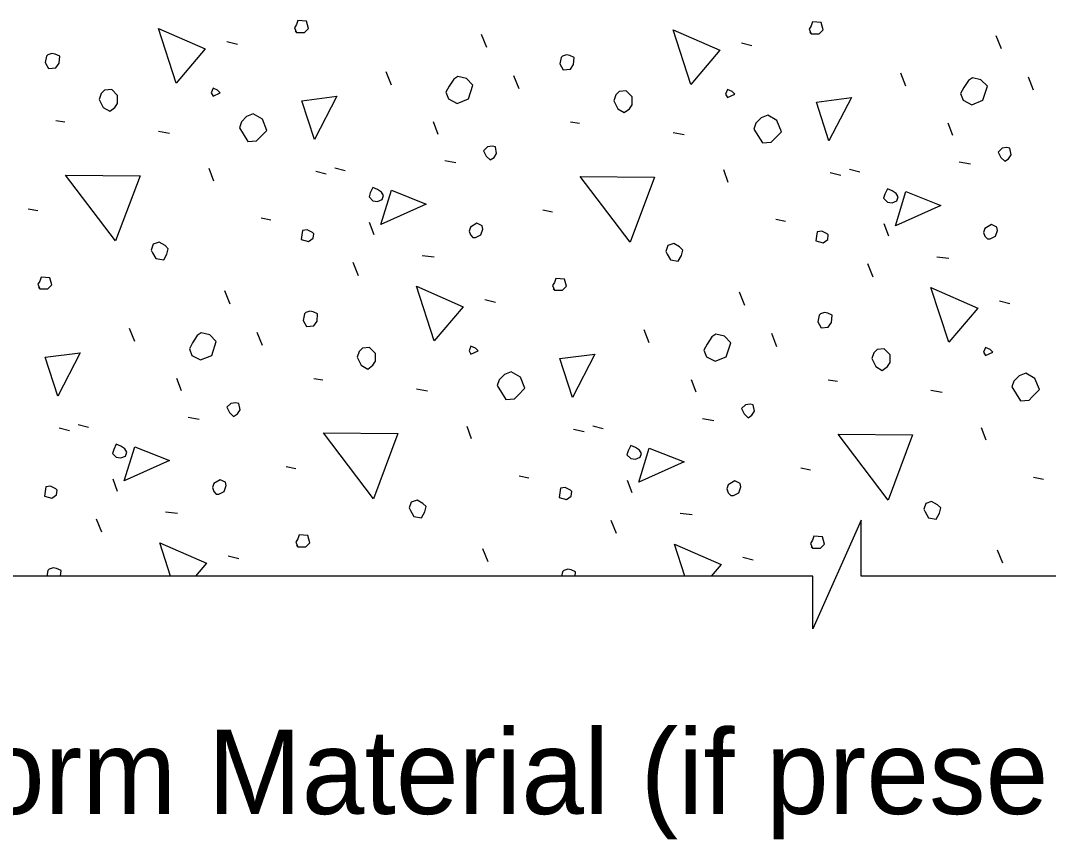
# Model space of a CAD drawing. Extents: x 0 to 15.4, y 0 to 9.7.
# Drawn here: x 4.079 to 5, y 1.736 to 2.469 of the extents above; entities that cross this region are included whole.
import ezdxf

# ---------------------------------------------------------------- set-up
doc = ezdxf.new("R2010")
doc.units = 0
doc.layers.add('Dimension', color=7, linetype='Continuous')
doc.layers.add('Miscellaneous', color=7, linetype='Continuous')

msp = doc.modelspace()

# ---------------------------------------------------------------- linework, layer by layer
at = {"layer": 'Dimension'}
for points in [[(4.21342, 1.97126), (3.76363, 1.97126), (3.76363, 2.02147), (3.7205, 1.92417), (3.7205, 1.97126), (3.21967, 1.97126)], [(5.47696, 1.97126), (4.8318, 1.97126), (4.8318, 2.02147), (4.78868, 1.92417), (4.78868, 1.97126), (4.21342, 1.97126)]]:
    msp.add_lwpolyline(points, dxfattribs=at)
at = {"layer": 'Miscellaneous'}
for p, q in [((4.26383, 2.45024), (4.27325, 2.44788)), ((4.49658, 2.44494), (4.49187, 2.45672)), ((4.72462, 2.44906), (4.73405, 2.44671)), ((4.95738, 2.44376), (4.95267, 2.45554)), ((4.41114, 2.41135), (4.40643, 2.42314)), ((4.87194, 2.41017), (4.86722, 2.42196)), ((4.52546, 2.40781), (4.52074, 2.4196)), ((4.98625, 2.40664), (4.98154, 2.41842)), ((4.11062, 2.37953), (4.11887, 2.37835)), ((4.45298, 2.36716), (4.44885, 2.37835)), ((4.57142, 2.37835), (4.57967, 2.37717)), ((4.91378, 2.36598), (4.90965, 2.37717)), ((4.20254, 2.3701), (4.21256, 2.36833)), ((4.66334, 2.36892), (4.67336, 2.36716)), ((4.45887, 2.34359), (4.46889, 2.34182)), ((4.91967, 2.34241), (4.92969, 2.34064)), ((4.25204, 2.32532), (4.24792, 2.33651)), ((4.34338, 2.33416), (4.3528, 2.3318)), ((4.36046, 2.3371), (4.36989, 2.33475)), ((4.71284, 2.32414), (4.70871, 2.33534)), ((4.80417, 2.33298), (4.8136, 2.33062)), ((4.82126, 2.33593), (4.83069, 2.33357)), ((4.08587, 2.30057), (4.09471, 2.2988)), ((4.29447, 2.29232), (4.30331, 2.29055)), ((4.54667, 2.29939), (4.55551, 2.29762)), ((4.39582, 2.277), (4.3917, 2.2882)), ((4.75527, 2.29114), (4.7641, 2.28937)), ((4.85662, 2.27582), (4.85249, 2.28702)), ((4.43884, 2.25873), (4.44944, 2.25755)), ((4.89963, 2.25755), (4.91024, 2.25638)), ((4.38168, 2.24047), (4.37696, 2.25225)), ((4.84248, 2.23929), (4.83776, 2.25107)), ((4.26677, 2.21513), (4.26206, 2.22691)), ((4.49482, 2.21925), (4.50424, 2.2169)), ((4.72757, 2.21395), (4.72286, 2.22573)), ((4.95561, 2.21807), (4.96504, 2.21572)), ((4.18133, 2.18154), (4.17662, 2.19333)), ((4.64213, 2.18036), (4.63741, 2.19215)), ((4.29565, 2.178), (4.29093, 2.18979)), ((4.75644, 2.17683), (4.75173, 2.18861)), ((4.22317, 2.13735), (4.21904, 2.14854)), ((4.34161, 2.14854), (4.34986, 2.14736)), ((4.68397, 2.13617), (4.67984, 2.14736)), ((4.80241, 2.14736), (4.81066, 2.14619)), ((4.43353, 2.13911), (4.44355, 2.13735)), ((4.89433, 2.13794), (4.90435, 2.13617)), ((4.22906, 2.11378), (4.23908, 2.11201)), ((4.68986, 2.1126), (4.69988, 2.11083)), ((4.11357, 2.10435), (4.12299, 2.10199)), ((4.13066, 2.10729), (4.14008, 2.10494)), ((4.48303, 2.09433), (4.47891, 2.10553)), ((4.57436, 2.10317), (4.58379, 2.10081)), ((4.59145, 2.10612), (4.60088, 2.10376)), ((4.94383, 2.09315), (4.9397, 2.10435)), ((4.31686, 2.06958), (4.3257, 2.06781)), ((4.77766, 2.0684), (4.7865, 2.06664)), ((4.16601, 2.04719), (4.16189, 2.05839)), ((4.52546, 2.06133), (4.5343, 2.05956)), ((4.62681, 2.04601), (4.62268, 2.05721)), ((4.98625, 2.06015), (4.99509, 2.05839)), ((4.20903, 2.02892), (4.21963, 2.02774)), ((4.66982, 2.02774), (4.68043, 2.02657)), ((4.15187, 2.01066), (4.14715, 2.02244)), ((4.61267, 2.00948), (4.60795, 2.02126)), ((4.26501, 1.98944), (4.27443, 1.98709)), ((4.49776, 1.98414), (4.49305, 1.99592)), ((4.7258, 1.98826), (4.73523, 1.98591)), ((4.95856, 1.98296), (4.95385, 1.99475))]:
    msp.add_line(p, q, dxfattribs=at)
for points in [[(4.32629, 2.45849), (4.33336, 2.45849), (4.33689, 2.46203), (4.33513, 2.46851), (4.32747, 2.4691), (4.32629, 2.46556), (4.32452, 2.46262), (4.32629, 2.45849), (4.32511, 2.45967)], [(4.78709, 2.45731), (4.79416, 2.45731), (4.79769, 2.46085), (4.79592, 2.46733), (4.78826, 2.46792), (4.78709, 2.46438), (4.78532, 2.46144), (4.78709, 2.45731), (4.78591, 2.45849)], [(4.21845, 2.41312), (4.20254, 2.46203), (4.24438, 2.44376), (4.21845, 2.41312)], [(4.67925, 2.41194), (4.66334, 2.46085), (4.70518, 2.44258), (4.67925, 2.41194)], [(4.10119, 2.43138), (4.10414, 2.42608), (4.11062, 2.42667), (4.11357, 2.4308), (4.11416, 2.43728), (4.11003, 2.43905), (4.10708, 2.43963), (4.10355, 2.43846), (4.10237, 2.43728), (4.10119, 2.43138)], [(4.56199, 2.43021), (4.56494, 2.4249), (4.57142, 2.42549), (4.57436, 2.42962), (4.57495, 2.4361), (4.57083, 2.43787), (4.56788, 2.43846), (4.56435, 2.43728), (4.56317, 2.4361), (4.56199, 2.43021)], [(4.46241, 2.39898), (4.47007, 2.39485), (4.48008, 2.39898), (4.48421, 2.41135), (4.47832, 2.41724), (4.47066, 2.41901), (4.46712, 2.41665), (4.463, 2.41017), (4.46005, 2.40487), (4.46241, 2.39898)], [(4.9232, 2.3978), (4.93086, 2.39367), (4.94088, 2.3978), (4.94501, 2.41017), (4.93911, 2.41606), (4.93145, 2.41783), (4.92792, 2.41547), (4.92379, 2.40899), (4.92085, 2.40369), (4.9232, 2.3978)], [(4.14951, 2.39839), (4.15305, 2.39132), (4.15894, 2.38778), (4.16365, 2.39132), (4.16601, 2.39485), (4.16601, 2.40192), (4.16071, 2.40723), (4.15423, 2.40664), (4.15128, 2.40369), (4.14951, 2.39839)], [(4.25145, 2.40133), (4.25793, 2.40428), (4.25558, 2.40664), (4.25145, 2.4084), (4.24968, 2.40428), (4.25145, 2.40133)], [(4.61031, 2.39721), (4.61384, 2.39014), (4.61974, 2.3866), (4.62445, 2.39014), (4.62681, 2.39367), (4.62681, 2.40074), (4.62151, 2.40605), (4.61502, 2.40546), (4.61208, 2.40251), (4.61031, 2.39721)], [(4.71225, 2.40015), (4.71873, 2.4031), (4.71638, 2.40546), (4.71225, 2.40723), (4.71048, 2.4031), (4.71225, 2.40015)], [(4.3422, 2.36244), (4.331, 2.39721), (4.36223, 2.40133), (4.3422, 2.36244)], [(4.803, 2.36126), (4.7918, 2.39603), (4.82303, 2.40015), (4.803, 2.36126)], [(4.27502, 2.37305), (4.28268, 2.36067), (4.29034, 2.36126), (4.29329, 2.36421), (4.29977, 2.37069), (4.29565, 2.38071), (4.2874, 2.38542), (4.2815, 2.38307), (4.27679, 2.37835), (4.27502, 2.37305)], [(4.73582, 2.37187), (4.74348, 2.3595), (4.75114, 2.36008), (4.75409, 2.36303), (4.76057, 2.36951), (4.75644, 2.37953), (4.74819, 2.38424), (4.7423, 2.38189), (4.73759, 2.37717), (4.73582, 2.37187)], [(4.49599, 2.34771), (4.49953, 2.34418), (4.50306, 2.34653), (4.50542, 2.35007), (4.50424, 2.35596), (4.5013, 2.35655), (4.49717, 2.35596), (4.49364, 2.35242), (4.49599, 2.34771)], [(4.95679, 2.34653), (4.96033, 2.343), (4.96386, 2.34535), (4.96622, 2.34889), (4.96504, 2.35478), (4.96209, 2.35537), (4.95797, 2.35478), (4.95443, 2.35125), (4.95679, 2.34653)], [(4.16424, 2.2717), (4.11946, 2.33062), (4.18605, 2.33003), (4.16424, 2.2717)], [(4.62504, 2.27052), (4.58026, 2.32944), (4.64684, 2.32885), (4.62504, 2.27052)], [(4.39464, 2.30764), (4.39877, 2.30705), (4.40289, 2.30882), (4.40407, 2.31236), (4.4023, 2.3153), (4.39877, 2.31766), (4.39464, 2.31943), (4.39228, 2.31471), (4.39111, 2.31118), (4.39464, 2.30764)], [(4.40171, 2.28643), (4.41114, 2.31707), (4.44237, 2.30469), (4.40171, 2.28643)], [(4.85544, 2.30646), (4.85956, 2.30587), (4.86369, 2.30764), (4.86487, 2.31118), (4.8631, 2.31412), (4.85956, 2.31648), (4.85544, 2.31825), (4.85308, 2.31353), (4.8519, 2.31), (4.85544, 2.30646)], [(4.86251, 2.28525), (4.87194, 2.31589), (4.90317, 2.30352), (4.86251, 2.28525)], [(4.48421, 2.27464), (4.48657, 2.27464), (4.49128, 2.277), (4.49305, 2.2823), (4.49246, 2.28525), (4.48774, 2.28761), (4.48185, 2.28407), (4.48067, 2.28054), (4.48185, 2.277), (4.48421, 2.27464)], [(4.94501, 2.27346), (4.94736, 2.27346), (4.95208, 2.27582), (4.95385, 2.28112), (4.95326, 2.28407), (4.94854, 2.28643), (4.94265, 2.28289), (4.94147, 2.27936), (4.94265, 2.27582), (4.94501, 2.27346)], [(4.33041, 2.27288), (4.33689, 2.27111), (4.34102, 2.27405), (4.34161, 2.27818), (4.34043, 2.27936), (4.33572, 2.28171), (4.33159, 2.28112), (4.331, 2.277), (4.33041, 2.27288)], [(4.79121, 2.2717), (4.79769, 2.26993), (4.80182, 2.27288), (4.80241, 2.277), (4.80123, 2.27818), (4.79651, 2.28054), (4.79239, 2.27995), (4.7918, 2.27582), (4.79121, 2.2717)], [(4.19724, 2.26109), (4.20019, 2.25579), (4.20726, 2.25461), (4.2102, 2.25991), (4.21138, 2.26463), (4.20844, 2.26757), (4.20313, 2.27052), (4.19783, 2.26875), (4.19606, 2.26345), (4.19724, 2.26109)], [(4.65804, 2.25991), (4.66099, 2.25461), (4.66806, 2.25343), (4.671, 2.25873), (4.67218, 2.26345), (4.66923, 2.26639), (4.66393, 2.26934), (4.65863, 2.26757), (4.65686, 2.26227), (4.65804, 2.25991)], [(4.09648, 2.22868), (4.10355, 2.22868), (4.10708, 2.23222), (4.10532, 2.2387), (4.09766, 2.23929), (4.09648, 2.23575), (4.09471, 2.23281), (4.09648, 2.22868), (4.0953, 2.22986)], [(4.55728, 2.2275), (4.56435, 2.2275), (4.56788, 2.23104), (4.56611, 2.23752), (4.55845, 2.23811), (4.55728, 2.23457), (4.55551, 2.23163), (4.55728, 2.2275), (4.5561, 2.22868)], [(4.44944, 2.18213), (4.43353, 2.23104), (4.47537, 2.21277), (4.44944, 2.18213)], [(4.91024, 2.18095), (4.89433, 2.22986), (4.93617, 2.21159), (4.91024, 2.18095)], [(4.33218, 2.2004), (4.33513, 2.19509), (4.34161, 2.19568), (4.34455, 2.19981), (4.34514, 2.20629), (4.34102, 2.20806), (4.33807, 2.20865), (4.33454, 2.20747), (4.33336, 2.20629), (4.33218, 2.2004)], [(4.79298, 2.19922), (4.79592, 2.19391), (4.80241, 2.1945), (4.80535, 2.19863), (4.80594, 2.20511), (4.80182, 2.20688), (4.79887, 2.20747), (4.79534, 2.20629), (4.79416, 2.20511), (4.79298, 2.19922)], [(4.2326, 2.16917), (4.24026, 2.16504), (4.25027, 2.16917), (4.2544, 2.18154), (4.24851, 2.18743), (4.24085, 2.1892), (4.23731, 2.18684), (4.23319, 2.18036), (4.23024, 2.17506), (4.2326, 2.16917)], [(4.69339, 2.16799), (4.70105, 2.16386), (4.71107, 2.16799), (4.7152, 2.18036), (4.7093, 2.18625), (4.70164, 2.18802), (4.69811, 2.18567), (4.69398, 2.17918), (4.69104, 2.17388), (4.69339, 2.16799)], [(4.3805, 2.1674), (4.38403, 2.16033), (4.38993, 2.15679), (4.39464, 2.16033), (4.397, 2.16386), (4.397, 2.17093), (4.3917, 2.17624), (4.38521, 2.17565), (4.38227, 2.1727), (4.3805, 2.1674)], [(4.48244, 2.17034), (4.48892, 2.17329), (4.48657, 2.17565), (4.48244, 2.17742), (4.48067, 2.17329), (4.48244, 2.17034)], [(4.8413, 2.16622), (4.84483, 2.15915), (4.85073, 2.15561), (4.85544, 2.15915), (4.8578, 2.16268), (4.8578, 2.16976), (4.85249, 2.17506), (4.84601, 2.17447), (4.84307, 2.17152), (4.8413, 2.16622)], [(4.94324, 2.16917), (4.94972, 2.17211), (4.94736, 2.17447), (4.94324, 2.17624), (4.94147, 2.17211), (4.94324, 2.16917)], [(4.11239, 2.13263), (4.10119, 2.1674), (4.13242, 2.17152), (4.11239, 2.13263)], [(4.57319, 2.13145), (4.56199, 2.16622), (4.59322, 2.17034), (4.57319, 2.13145)], [(4.50601, 2.14206), (4.51367, 2.12969), (4.52133, 2.13028), (4.52428, 2.13322), (4.53076, 2.1397), (4.52663, 2.14972), (4.51839, 2.15443), (4.51249, 2.15208), (4.50778, 2.14736), (4.50601, 2.14206)], [(4.96681, 2.14088), (4.97447, 2.12851), (4.98213, 2.1291), (4.98508, 2.13204), (4.99156, 2.13852), (4.98743, 2.14854), (4.97918, 2.15326), (4.97329, 2.1509), (4.96858, 2.14619), (4.96681, 2.14088)], [(4.26618, 2.1179), (4.26972, 2.11437), (4.27325, 2.11672), (4.27561, 2.12026), (4.27443, 2.12615), (4.27149, 2.12674), (4.26736, 2.12615), (4.26383, 2.12261), (4.26618, 2.1179)], [(4.72698, 2.11672), (4.73052, 2.11319), (4.73405, 2.11554), (4.73641, 2.11908), (4.73523, 2.12497), (4.73229, 2.12556), (4.72816, 2.12497), (4.72462, 2.12144), (4.72698, 2.11672)], [(4.39523, 2.04071), (4.35045, 2.09963), (4.41703, 2.09904), (4.39523, 2.04071)], [(4.16483, 2.07783), (4.16896, 2.07724), (4.17308, 2.07901), (4.17426, 2.08255), (4.17249, 2.08549), (4.16896, 2.08785), (4.16483, 2.08962), (4.16247, 2.0849), (4.1613, 2.08137), (4.16483, 2.07783)], [(4.85603, 2.03953), (4.81125, 2.09846), (4.87783, 2.09787), (4.85603, 2.03953)], [(4.1719, 2.05662), (4.18133, 2.08726), (4.21256, 2.07489), (4.1719, 2.05662)], [(4.62563, 2.07665), (4.62975, 2.07606), (4.63388, 2.07783), (4.63506, 2.08137), (4.63329, 2.08431), (4.62975, 2.08667), (4.62563, 2.08844), (4.62327, 2.08372), (4.62209, 2.08019), (4.62563, 2.07665)], [(4.6327, 2.05544), (4.64213, 2.08608), (4.67336, 2.07371), (4.6327, 2.05544)], [(4.2544, 2.04483), (4.25676, 2.04483), (4.26147, 2.04719), (4.26324, 2.05249), (4.26265, 2.05544), (4.25793, 2.0578), (4.25204, 2.05426), (4.25086, 2.05073), (4.25204, 2.04719), (4.2544, 2.04483)], [(4.7152, 2.04365), (4.71755, 2.04365), (4.72227, 2.04601), (4.72404, 2.05131), (4.72345, 2.05426), (4.71873, 2.05662), (4.71284, 2.05308), (4.71166, 2.04955), (4.71284, 2.04601), (4.7152, 2.04365)], [(4.1006, 2.04307), (4.10708, 2.0413), (4.11121, 2.04424), (4.1118, 2.04837), (4.11062, 2.04955), (4.10591, 2.0519), (4.10178, 2.05131), (4.10119, 2.04719), (4.1006, 2.04307)], [(4.5614, 2.04189), (4.56788, 2.04012), (4.57201, 2.04307), (4.5726, 2.04719), (4.57142, 2.04837), (4.5667, 2.05073), (4.56258, 2.05014), (4.56199, 2.04601), (4.5614, 2.04189)], [(4.42823, 2.0301), (4.43118, 2.0248), (4.43825, 2.02362), (4.44119, 2.02892), (4.44237, 2.03364), (4.43943, 2.03658), (4.43412, 2.03953), (4.42882, 2.03776), (4.42705, 2.03246), (4.42823, 2.0301)], [(4.88903, 2.02892), (4.89197, 2.02362), (4.89904, 2.02244), (4.90199, 2.02774), (4.90317, 2.03246), (4.90022, 2.03541), (4.89492, 2.03835), (4.88962, 2.03658), (4.88785, 2.03128), (4.88903, 2.02892)], [(4.32747, 1.99769), (4.33454, 1.99769), (4.33807, 2.00123), (4.33631, 2.00771), (4.32864, 2.0083), (4.32747, 2.00476), (4.3257, 2.00182), (4.32747, 1.99769), (4.32629, 1.99887)], [(4.78826, 1.99651), (4.79534, 1.99651), (4.79887, 2.00005), (4.7971, 2.00653), (4.78944, 2.00712), (4.78826, 2.00359), (4.7865, 2.00064), (4.78826, 1.99651), (4.78709, 1.99769)], [(4.21346, 1.9713), (4.20372, 2.00123), (4.24556, 1.98296), (4.23569, 1.9713)], [(4.67387, 1.9713), (4.66452, 2.00005), (4.70636, 1.98178), (4.69749, 1.9713)], [(4.11486, 1.9713), (4.11533, 1.97648), (4.11121, 1.97825), (4.10826, 1.97884), (4.10473, 1.97766), (4.10355, 1.97648), (4.10251, 1.9713)], [(4.57577, 1.9713), (4.57613, 1.9753), (4.57201, 1.97707), (4.56906, 1.97766), (4.56553, 1.97648), (4.56435, 1.9753), (4.56355, 1.9713)]]:
    msp.add_lwpolyline(points, dxfattribs=at)

# ---------------------------------------------------------------- texts
at = {"layer": 'Dimension'}
msp.add_text('Form Material (if present) removed ', height=0.0756002, dxfattribs=at).set_placement((3.98269, 1.75831))

doc.saveas('drawing.dxf')
